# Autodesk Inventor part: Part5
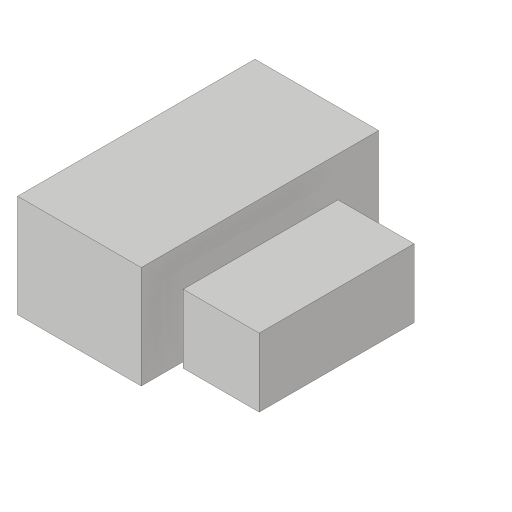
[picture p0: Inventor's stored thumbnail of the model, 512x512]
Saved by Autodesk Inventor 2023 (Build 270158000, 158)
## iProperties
Created: 2015-07
Part Number: Part5
Material: Generic
Document SubType Name: Modeling
Designer: Sandeep
Density: 1 g/cm^3
Appearance: Default
Author: Sandeep
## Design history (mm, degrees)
sketch "Sketch1"
  geometry: L1 (-7.411, 3.941)-(-1.385, 3.941); L2 (-1.385, 3.941)-(-1.385, -7.628); L3 (-1.385, -7.628)-(-7.411, -7.628); L4 (-7.411, -7.628)-(-7.411, 3.941); 1 further point
  constraints: 8 end point, 2 parallel, 1 horizontal, 1 perpendicular
extrude "Extrusion1" new body sketch "Sketch1" distance "d0" = 5; taper "d1" = 0 deg
sketch "Sketch2"
  geometry: L1 (1.52, -7.467)-(7.078, -7.467); L2 (7.078, -7.467)-(7.078, 3.854); L3 (7.078, 3.854)-(1.52, 3.854); L4 (1.52, 3.854)-(1.52, -7.467); 1 further point
  constraints: 8 end point, 2 parallel, 1 horizontal, 1 perpendicular
extrude "Extrusion2" new body sketch "Sketch2" distance "d2" = 5; taper "d3" = 0 deg
node "Direct Edit1"
body "Solid1"
body "Solid2"
feature "Scale1"
other parameters: "d4" = 15
